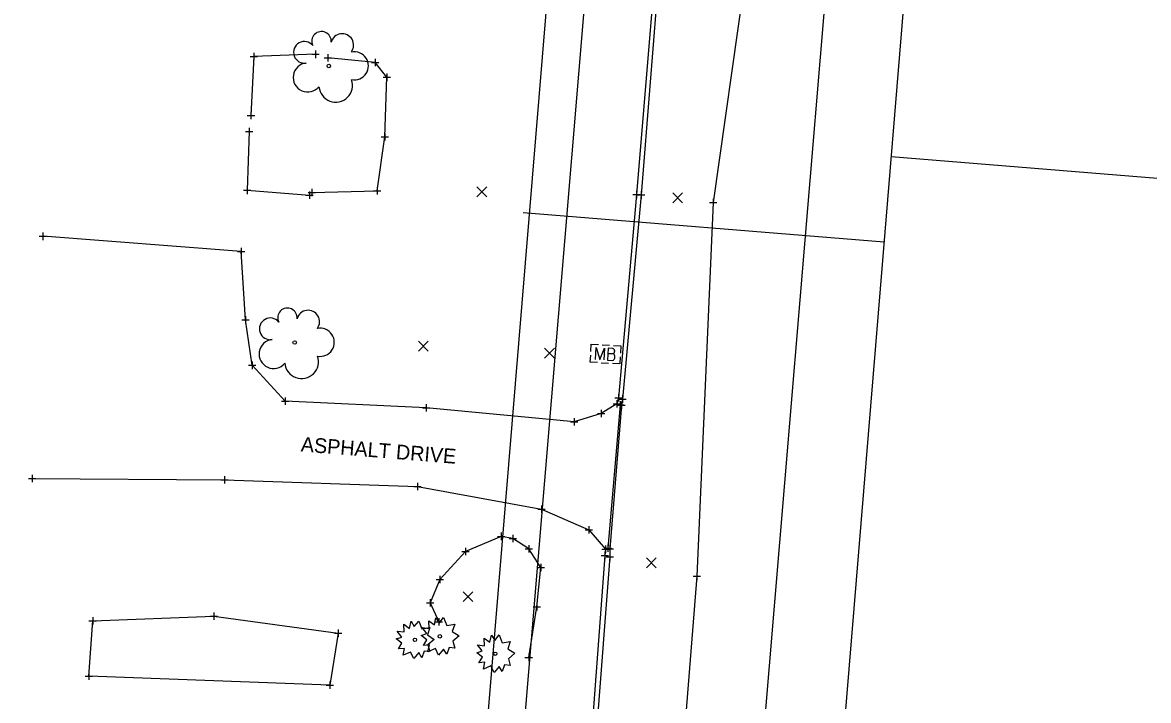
# Model space of a CAD drawing. Extents: x 1380440 to 1381945, y 468756 to 470369.
# Drawn here: x 1381467.5 to 1381620.2, y 469470 to 469561.9 of the extents above; entities that cross this region are included whole.
import ezdxf

# ---------------------------------------------------------------- set-up
doc = ezdxf.new("R2010")
doc.units = 0
for name, color, linetype in [('DR_P_Storm_Sewer', 7, 'Continuous'), ('DR_X_Cells', 7, 'Continuous'), ('GE_P_Driveway_CL', 7, 'Continuous'), ('GK_Drainage_Nodes', 7, 'Continuous'), ('PM_X_CL_Double_Solid', 7, 'Continuous'), ('RD_P_Cells', 7, 'Continuous'), ('RW_P_Esmt_TMP', 7, 'Continuous'), ('RW_X_Esmt_SH', 7, 'Continuous'), ('SC_Scratch10', 7, 'Continuous'), ('SC_Scratch11', 7, 'Continuous'), ('SC_Shading1', 7, 'Continuous'), ('SH_Named_Boundary', 7, 'Continuous'), ('UT_X_Gas', 7, 'Continuous'), ('UT_X_Overhead_Combined', 7, 'Continuous'), ('UT_X_Sanitary_Line', 7, 'Continuous'), ('UT_X_Water', 7, 'Continuous'), ('X-SUBDIVISION', 7, 'Continuous')]:
    doc.layers.add(name, color=color, linetype=linetype)

msp = doc.modelspace()

# ---------------------------------------------------------------- linework, layer by layer
at = {"layer": 'DR_P_Storm_Sewer'}
for points in [[(1381506.76, 469538.86), (1381515.58, 469539.12), (1381516.63, 469546.43), (1381516.9, 469554.53), (1381515.34, 469556.5), (1381508.92, 469557.14)], [(1381536.15, 469475.8), (1381537.25, 469482.65), (1381537.81, 469488.02), (1381536.18, 469490.54), (1381534.02, 469491.94), (1381532.41, 469492.23), (1381527.6, 469490.19), (1381524.12, 469486.36), (1381522.77, 469483.2), (1381523.96, 469480.62)]]:
    msp.add_lwpolyline(points, dxfattribs=at)
at = {"layer": 'DR_X_Cells'}
for points in [[(1381553.19, 469568.93), (1381553.23, 469567.99), (1381550.79, 469538.62), (1381548.32, 469511.01), (1381548.12, 469510.21)], [(1381546.56, 469490.49), (1381546.46, 469489.61), (1381542.99, 469442.93), (1381540.42, 469414.14), (1381540.26, 469413.42)]]:
    msp.add_lwpolyline(points, dxfattribs=at)
at = {"layer": 'GE_P_Driveway_CL'}
for p, q in [((1381529.13, 469538.3), (1381530.47, 469539.63)), ((1381529.13, 469539.63), (1381530.47, 469538.3)), ((1381555.69, 469537.49), (1381557.02, 469538.83)), ((1381555.69, 469538.83), (1381557.02, 469537.49)), ((1381521.21, 469517.37), (1381522.54, 469518.71)), ((1381521.21, 469518.71), (1381522.54, 469517.37)), ((1381538.3, 469516.42), (1381539.63, 469517.76)), ((1381538.3, 469517.76), (1381539.63, 469516.42)), ((1381552.13, 469487.96), (1381553.46, 469489.3)), ((1381552.13, 469489.3), (1381553.46, 469487.96)), ((1381527.25, 469483.38), (1381528.58, 469484.72)), ((1381527.25, 469484.72), (1381528.58, 469483.38))]:
    msp.add_line(p, q, dxfattribs=at)
at = {"layer": 'GK_Drainage_Nodes'}
for points in [[(1381507.23, 469557.62), (1381498.89, 469557.34), (1381498.49, 469549.33)], [(1381498.26, 469547.17), (1381497.97, 469539.17), (1381506.42, 469538.51)]]:
    msp.add_lwpolyline(points, dxfattribs=at)
at = {"layer": 'PM_X_CL_Double_Solid'}
msp.add_lwpolyline([(1381618.76, 470220.14), (1381616.92, 470200.19), (1381615.1, 470178.83), (1381610.95, 470124.78), (1381606.49, 470071.23), (1381602.26, 470019.36), (1381598.18, 469969.8), (1381595.01, 469928.06), (1381590.91, 469878.81), (1381589.36, 469859.11), (1381585.99, 469815.58), (1381581.29, 469760.78), (1381580.3, 469747.86), (1381578.72, 469729.45), (1381576.78, 469708.95), (1381575.29, 469689.79), (1381572.76, 469657.56), (1381569.36, 469615.7), (1381565.36, 469567.23), (1381561.16, 469537.52), (1381558.94, 469486.81), (1381555.39, 469442.03), (1381550.97, 469391.02)], dxfattribs=at)
at = {"layer": 'RD_P_Cells'}
for p, q in [((1381546.13, 469518.21), (1381547.13, 469518.15)), ((1381546.57, 469516.96), (1381546.57, 469516.96)), ((1381545.99, 469515.77), (1381546.99, 469515.71))]:
    msp.add_line(p, q, dxfattribs=at)
for points in [[(1381544.59, 469517.32), (1381544.64, 469518.29), (1381545.61, 469518.24)], [(1381545.23, 469516.23), (1381545.32, 469517.83), (1381545.81, 469516.2), (1381546.45, 469517.77), (1381546.36, 469516.17)], [(1381547.59, 469516.97), (1381547.66, 469517.03), (1381547.7, 469517.07), (1381547.73, 469517.1), (1381547.74, 469517.13), (1381547.77, 469517.18), (1381547.78, 469517.21), (1381547.81, 469517.3), (1381547.82, 469517.34), (1381547.82, 469517.39), (1381547.81, 469517.46), (1381547.79, 469517.53), (1381547.75, 469517.58), (1381547.69, 469517.64), (1381547.64, 469517.66), (1381547.62, 469517.68), (1381547.56, 469517.71), (1381546.94, 469517.74), (1381546.85, 469516.14), (1381547.55, 469516.1), (1381547.64, 469516.15), (1381547.72, 469516.21), (1381547.78, 469516.31), (1381547.83, 469516.42), (1381547.85, 469516.53), (1381547.85, 469516.6), (1381547.83, 469516.68), (1381547.79, 469516.8), (1381547.73, 469516.88), (1381547.59, 469516.97), (1381546.9, 469517.01)], [(1381547.64, 469518.12), (1381548.63, 469518.07), (1381548.58, 469517.1)], [(1381545.47, 469515.8), (1381544.51, 469515.85), (1381544.56, 469516.82)], [(1381548.55, 469516.6), (1381548.5, 469515.63), (1381547.51, 469515.68)]]:
    msp.add_lwpolyline(points, dxfattribs=at)
at = {"layer": 'RW_P_Esmt_TMP'}
msp.add_lwpolyline([(1381553.84, 469569.16), (1381551.39, 469538.56), (1381548.86, 469510.86), (1381548.72, 469510.03), (1381547.16, 469490.53), (1381547.16, 469489.45), (1381543.59, 469442.93), (1381541.04, 469414.11), (1381541, 469413.22), (1381539.53, 469394.02)], dxfattribs=at)
at = {"layer": 'RW_X_Esmt_SH'}
for points in [[(1381548.12, 469510.21), (1381545.98, 469508.88), (1381542.32, 469507.76), (1381522.23, 469509.67), (1381503.11, 469510.58), (1381498.63, 469515.43), (1381497.75, 469521.59), (1381497.16, 469530.86), (1381470.26, 469532.93)], [(1381548.12, 469510.21), (1381548.54, 469510.05), (1381546.9, 469490.64), (1381546.56, 469490.49)], [(1381468.81, 469500.07), (1381494.9, 469499.89), (1381521.09, 469499), (1381537.89, 469495.93), (1381544.32, 469493.13), (1381546.56, 469490.49)]]:
    msp.add_lwpolyline(points, dxfattribs=at)
at = {"layer": 'SC_Scratch10'}
for points in [[(1381520.63, 469480), (1381521.24, 469480.73), (1381521.65, 469479.68), (1381522.74, 469479.86), (1381522.41, 469478.85), (1381523.35, 469478.25), (1381522.49, 469477.52), (1381522.74, 469476.61), (1381521.99, 469476.67), (1381521.67, 469475.76), (1381521.24, 469476.45), (1381520.56, 469475.64), (1381520.13, 469476.52), (1381519.11, 469476.09), (1381519.3, 469477.03), (1381518.49, 469476.95), (1381518.96, 469477.74), (1381518.2, 469478.31), (1381518.93, 469478.57), (1381518.33, 469479.38), (1381519.26, 469479.27), (1381519.23, 469480.3), (1381519.98, 469479.74), (1381520.19, 469480.72), (1381520.63, 469480)], [(1381524.01, 469480.47), (1381524.62, 469481.21), (1381525.03, 469480.15), (1381526.13, 469480.33), (1381525.79, 469479.32), (1381526.73, 469478.73), (1381525.88, 469477.99), (1381526.13, 469477.08), (1381525.37, 469477.15), (1381525.05, 469476.23), (1381524.62, 469476.93), (1381523.94, 469476.11), (1381523.51, 469477), (1381522.49, 469476.57), (1381522.69, 469477.51), (1381521.87, 469477.42), (1381522.35, 469478.21), (1381521.58, 469478.78), (1381522.32, 469479.05), (1381521.71, 469479.85), (1381522.64, 469479.74), (1381522.61, 469480.78), (1381523.36, 469480.21), (1381523.57, 469481.19), (1381524.01, 469480.47)], [(1381531.54, 469478.11), (1381532.14, 469478.85), (1381532.56, 469477.8), (1381533.65, 469477.98), (1381533.31, 469476.96), (1381534.25, 469476.37), (1381533.4, 469475.63), (1381533.65, 469474.72), (1381532.89, 469474.79), (1381532.57, 469473.88), (1381532.14, 469474.57), (1381531.46, 469473.75), (1381531.03, 469474.64), (1381530.01, 469474.21), (1381530.21, 469475.15), (1381529.39, 469475.07), (1381529.87, 469475.86), (1381529.1, 469476.42), (1381529.84, 469476.69), (1381529.23, 469477.49), (1381530.16, 469477.38), (1381530.13, 469478.42), (1381530.89, 469477.85), (1381531.09, 469478.84), (1381531.54, 469478.11)]]:
    msp.add_lwpolyline(points, dxfattribs=at)
for centre, radius in [((1381509.04, 469556.03), 0.24), ((1381504.42, 469518.52), 0.24), ((1381524.1, 469478.66), 0.23), ((1381520.72, 469478.19), 0.23), ((1381531.62, 469476.3), 0.23)]:
    msp.add_circle(centre, radius, dxfattribs=at)
for centre, radius, start, end in [((1381508.05, 469559.39), 1.32, 354.0047, 205.9741), ((1381510.86, 469558.86), 1.55, 323.83, 165.0376), ((1381505.73, 469557.89), 1.47, 39.0625, 279.5412), ((1381512.5, 469556.06), 1.91, 259.1453, 101.4596), ((1381506.18, 469554.48), 1.97, 96.1722, 320.5737), ((1381509.98, 469553.42), 2.28, 184.9476, 19.4572), ((1381503.43, 469521.88), 1.32, 354.0047, 205.9741), ((1381501.11, 469520.38), 1.47, 39.0625, 279.5412), ((1381506.24, 469521.35), 1.55, 323.83, 165.0376), ((1381507.88, 469518.55), 1.91, 259.1453, 101.4596), ((1381501.56, 469516.97), 1.97, 96.1722, 320.5737), ((1381505.36, 469515.91), 2.28, 184.9476, 19.4572)]:
    msp.add_arc(centre, radius, start, end, dxfattribs=at)
at = {"layer": 'SC_Scratch11'}
msp.add_lwpolyline([(1381476.5, 469473.27), (1381477.02, 469480.75), (1381493.45, 469481.39), (1381510.3, 469479.11), (1381509.2, 469472.04)], close=True, dxfattribs=at)
at = {"layer": 'SC_Shading1'}
msp.add_lwpolyline([(1381589.36, 469859.11), (1381585.99, 469815.58), (1381581.29, 469760.78), (1381580.3, 469747.86), (1381578.72, 469729.45), (1381576.78, 469708.95), (1381575.29, 469689.79), (1381572.76, 469657.56), (1381569.36, 469615.7), (1381565.36, 469567.23), (1381561.16, 469537.52), (1381558.94, 469486.81), (1381555.39, 469442.03), (1381550.97, 469391.02)], dxfattribs=at)
at = {"layer": 'SH_Named_Boundary'}
for p, q in [((1381507.23, 469558.12), (1381507.23, 469557.12)), ((1381498.39, 469557.34), (1381499.39, 469557.34)), ((1381498.89, 469557.84), (1381498.89, 469556.84)), ((1381498.89, 469557.34), (1381498.89, 469557.34)), ((1381506.73, 469557.62), (1381507.73, 469557.62)), ((1381507.23, 469557.62), (1381507.23, 469557.62)), ((1381508.42, 469557.14), (1381509.42, 469557.14)), ((1381508.92, 469557.64), (1381508.92, 469556.64)), ((1381508.92, 469557.14), (1381508.92, 469557.14)), ((1381515.34, 469557), (1381515.34, 469556)), ((1381514.84, 469556.5), (1381515.84, 469556.5)), ((1381515.34, 469556.5), (1381515.34, 469556.5)), ((1381516.4, 469554.53), (1381517.4, 469554.53)), ((1381516.9, 469555.03), (1381516.9, 469554.03)), ((1381516.9, 469554.53), (1381516.9, 469554.53)), ((1381497.99, 469549.33), (1381498.99, 469549.33)), ((1381498.49, 469549.83), (1381498.49, 469548.83)), ((1381498.49, 469549.33), (1381498.49, 469549.33)), ((1381498.26, 469547.67), (1381498.26, 469546.67)), ((1381497.76, 469547.17), (1381498.76, 469547.17)), ((1381498.26, 469547.17), (1381498.26, 469547.17)), ((1381516.13, 469546.43), (1381517.13, 469546.43)), ((1381516.63, 469546.93), (1381516.63, 469545.93)), ((1381516.63, 469546.43), (1381516.63, 469546.43)), ((1381497.47, 469539.17), (1381498.47, 469539.17)), ((1381497.97, 469539.67), (1381497.97, 469538.67)), ((1381497.97, 469539.17), (1381497.97, 469539.17)), ((1381505.92, 469538.51), (1381506.92, 469538.51)), ((1381506.26, 469538.86), (1381507.26, 469538.86)), ((1381506.42, 469539.01), (1381506.42, 469538.01)), ((1381506.42, 469538.51), (1381506.42, 469538.51)), ((1381506.76, 469539.36), (1381506.76, 469538.36)), ((1381506.76, 469538.86), (1381506.76, 469538.86)), ((1381515.08, 469539.12), (1381516.08, 469539.12)), ((1381515.58, 469539.62), (1381515.58, 469538.62)), ((1381515.58, 469539.12), (1381515.58, 469539.12)), ((1381550.29, 469538.62), (1381551.29, 469538.62)), ((1381550.79, 469539.12), (1381550.79, 469538.12)), ((1381550.79, 469538.62), (1381550.79, 469538.62)), ((1381550.89, 469538.56), (1381551.89, 469538.56)), ((1381551.39, 469539.06), (1381551.39, 469538.06)), ((1381551.39, 469538.56), (1381551.39, 469538.56)), ((1381560.66, 469537.52), (1381561.66, 469537.52)), ((1381561.16, 469538.02), (1381561.16, 469537.02)), ((1381561.16, 469537.52), (1381561.16, 469537.52)), ((1381469.76, 469532.93), (1381470.76, 469532.93)), ((1381470.26, 469533.43), (1381470.26, 469532.43)), ((1381470.26, 469532.93), (1381470.26, 469532.93)), ((1381496.66, 469530.86), (1381497.66, 469530.86)), ((1381497.16, 469531.36), (1381497.16, 469530.36)), ((1381497.16, 469530.86), (1381497.16, 469530.86)), ((1381497.25, 469521.59), (1381498.25, 469521.59)), ((1381497.75, 469522.09), (1381497.75, 469521.09)), ((1381497.75, 469521.59), (1381497.75, 469521.59)), ((1381498.13, 469515.43), (1381499.13, 469515.43)), ((1381498.63, 469515.93), (1381498.63, 469514.93)), ((1381498.63, 469515.43), (1381498.63, 469515.43)), ((1381503.11, 469511.08), (1381503.11, 469510.08)), ((1381547.82, 469511.01), (1381548.82, 469511.01)), ((1381548.32, 469511.51), (1381548.32, 469510.51)), ((1381548.32, 469511.01), (1381548.32, 469511.01)), ((1381548.36, 469510.86), (1381549.36, 469510.86)), ((1381548.86, 469511.36), (1381548.86, 469510.36)), ((1381548.86, 469510.86), (1381548.86, 469510.86)), ((1381502.61, 469510.58), (1381503.61, 469510.58)), ((1381503.11, 469510.58), (1381503.11, 469510.58)), ((1381521.73, 469509.67), (1381522.73, 469509.67)), ((1381522.23, 469510.17), (1381522.23, 469509.17)), ((1381522.23, 469509.67), (1381522.23, 469509.67)), ((1381545.98, 469509.38), (1381545.98, 469508.38)), ((1381547.62, 469510.21), (1381548.62, 469510.21)), ((1381547.62, 469510.21), (1381548.62, 469510.21)), ((1381547.62, 469510.21), (1381548.62, 469510.21)), ((1381548.04, 469510.05), (1381549.04, 469510.05)), ((1381548.12, 469510.71), (1381548.12, 469509.71)), ((1381548.12, 469510.71), (1381548.12, 469509.71)), ((1381548.12, 469510.71), (1381548.12, 469509.71)), ((1381548.12, 469510.21), (1381548.12, 469510.21)), ((1381548.12, 469510.21), (1381548.12, 469510.21)), ((1381548.12, 469510.21), (1381548.12, 469510.21)), ((1381548.22, 469510.03), (1381549.22, 469510.03)), ((1381548.54, 469510.55), (1381548.54, 469509.55)), ((1381548.54, 469510.05), (1381548.54, 469510.05)), ((1381548.72, 469510.53), (1381548.72, 469509.53)), ((1381548.72, 469510.03), (1381548.72, 469510.03)), ((1381541.82, 469507.76), (1381542.82, 469507.76)), ((1381542.32, 469508.26), (1381542.32, 469507.26)), ((1381542.32, 469507.76), (1381542.32, 469507.76)), ((1381545.48, 469508.88), (1381546.48, 469508.88)), ((1381545.98, 469508.88), (1381545.98, 469508.88)), ((1381468.31, 469500.07), (1381469.31, 469500.07)), ((1381468.81, 469500.57), (1381468.81, 469499.57)), ((1381468.81, 469500.07), (1381468.81, 469500.07)), ((1381494.9, 469500.39), (1381494.9, 469499.39)), ((1381494.4, 469499.89), (1381495.4, 469499.89)), ((1381494.9, 469499.89), (1381494.9, 469499.89)), ((1381520.59, 469499), (1381521.59, 469499)), ((1381521.09, 469499.5), (1381521.09, 469498.5)), ((1381521.09, 469499), (1381521.09, 469499)), ((1381537.39, 469495.93), (1381538.39, 469495.93)), ((1381537.89, 469496.43), (1381537.89, 469495.43)), ((1381537.89, 469495.93), (1381537.89, 469495.93)), ((1381532.41, 469492.73), (1381532.41, 469491.73)), ((1381534.02, 469492.44), (1381534.02, 469491.44)), ((1381543.82, 469493.13), (1381544.82, 469493.13)), ((1381544.32, 469493.63), (1381544.32, 469492.63)), ((1381544.32, 469493.13), (1381544.32, 469493.13)), ((1381531.91, 469492.23), (1381532.91, 469492.23)), ((1381532.41, 469492.23), (1381532.41, 469492.23)), ((1381533.52, 469491.94), (1381534.52, 469491.94)), ((1381534.02, 469491.94), (1381534.02, 469491.94)), ((1381536.18, 469491.04), (1381536.18, 469490.04)), ((1381546.56, 469490.99), (1381546.56, 469489.99)), ((1381546.56, 469490.99), (1381546.56, 469489.99)), ((1381546.56, 469490.99), (1381546.56, 469489.99)), ((1381546.9, 469491.14), (1381546.9, 469490.14)), ((1381547.16, 469491.03), (1381547.16, 469490.03)), ((1381527.1, 469490.19), (1381528.1, 469490.19)), ((1381527.6, 469490.69), (1381527.6, 469489.69)), ((1381527.6, 469490.19), (1381527.6, 469490.19)), ((1381535.68, 469490.54), (1381536.68, 469490.54)), ((1381536.18, 469490.54), (1381536.18, 469490.54)), ((1381545.96, 469489.61), (1381546.96, 469489.61)), ((1381546.06, 469490.49), (1381547.06, 469490.49)), ((1381546.06, 469490.49), (1381547.06, 469490.49)), ((1381546.06, 469490.49), (1381547.06, 469490.49)), ((1381546.4, 469490.64), (1381547.4, 469490.64)), ((1381546.46, 469490.11), (1381546.46, 469489.11)), ((1381546.46, 469489.61), (1381546.46, 469489.61)), ((1381546.56, 469490.49), (1381546.56, 469490.49)), ((1381546.56, 469490.49), (1381546.56, 469490.49)), ((1381546.56, 469490.49), (1381546.56, 469490.49)), ((1381546.66, 469490.53), (1381547.66, 469490.53)), ((1381546.66, 469489.45), (1381547.66, 469489.45)), ((1381546.9, 469490.64), (1381546.9, 469490.64)), ((1381547.16, 469490.53), (1381547.16, 469490.53)), ((1381547.16, 469489.95), (1381547.16, 469488.95)), ((1381547.16, 469489.45), (1381547.16, 469489.45)), ((1381537.31, 469488.02), (1381538.31, 469488.02)), ((1381537.81, 469488.52), (1381537.81, 469487.52)), ((1381537.81, 469488.02), (1381537.81, 469488.02)), ((1381523.62, 469486.36), (1381524.62, 469486.36)), ((1381524.12, 469486.86), (1381524.12, 469485.86)), ((1381524.12, 469486.36), (1381524.12, 469486.36)), ((1381558.44, 469486.81), (1381559.44, 469486.81)), ((1381558.94, 469487.31), (1381558.94, 469486.31)), ((1381558.94, 469486.81), (1381558.94, 469486.81)), ((1381522.77, 469483.7), (1381522.77, 469482.7)), ((1381493.45, 469481.89), (1381493.45, 469480.89)), ((1381522.27, 469483.2), (1381523.27, 469483.2)), ((1381522.77, 469483.2), (1381522.77, 469483.2)), ((1381536.75, 469482.65), (1381537.75, 469482.65)), ((1381537.25, 469483.15), (1381537.25, 469482.15)), ((1381537.25, 469482.65), (1381537.25, 469482.65)), ((1381476.52, 469480.75), (1381477.52, 469480.75)), ((1381477.02, 469481.25), (1381477.02, 469480.25)), ((1381477.02, 469480.75), (1381477.02, 469480.75)), ((1381492.95, 469481.39), (1381493.95, 469481.39)), ((1381493.45, 469481.39), (1381493.45, 469481.39)), ((1381523.46, 469480.62), (1381524.46, 469480.62)), ((1381523.96, 469481.12), (1381523.96, 469480.12)), ((1381523.96, 469480.62), (1381523.96, 469480.62)), ((1381509.8, 469479.11), (1381510.8, 469479.11)), ((1381510.3, 469479.61), (1381510.3, 469478.61)), ((1381510.3, 469479.11), (1381510.3, 469479.11)), ((1381535.65, 469475.8), (1381536.65, 469475.8)), ((1381536.15, 469476.3), (1381536.15, 469475.3)), ((1381536.15, 469475.8), (1381536.15, 469475.8)), ((1381476, 469473.27), (1381477, 469473.27)), ((1381476.5, 469473.77), (1381476.5, 469472.77)), ((1381476.5, 469473.27), (1381476.5, 469473.27)), ((1381508.7, 469472.04), (1381509.7, 469472.04)), ((1381509.2, 469472.54), (1381509.2, 469471.54)), ((1381509.2, 469472.04), (1381509.2, 469472.04))]:
    msp.add_line(p, q, dxfattribs=at)
at = {"layer": 'UT_X_Gas'}
msp.add_lwpolyline([(1381485.9, 468926.41), (1381594.27, 470237.89), (1380558, 470279.29)], dxfattribs=at)
at = {"layer": 'UT_X_Overhead_Combined'}
msp.add_lwpolyline([(1381540.8, 469054.26), (1381515.28, 469203.1), (1381529.17, 469390.12), (1381543.86, 469565.78), (1381559.77, 469757.41), (1381571.97, 469887.64), (1381581.26, 470018.2), (1381595.79, 470220.83), (1381665.56, 470247.4)], dxfattribs=at)
at = {"layer": 'UT_X_Sanitary_Line'}
for p, q in [((1381576.01, 469430.09), (1381599.15, 469712.1)), ((1381634.32, 469539.73), (1381585.33, 469543.71)), ((1381584.38, 469532.13), (1381535.39, 469536.11))]:
    msp.add_line(p, q, dxfattribs=at)
at = {"layer": 'UT_X_Water'}
msp.add_line((1381545.41, 469194.71), (1381630.26, 470209.69), dxfattribs=at)

# ---------------------------------------------------------------- texts
at = {"layer": 'X-SUBDIVISION'}
msp.add_text('ASPHALT DRIVE', height=2, rotation=355.4428, dxfattribs=at).set_placement((1381505.2, 469503.75))

doc.saveas('drawing.dxf')
